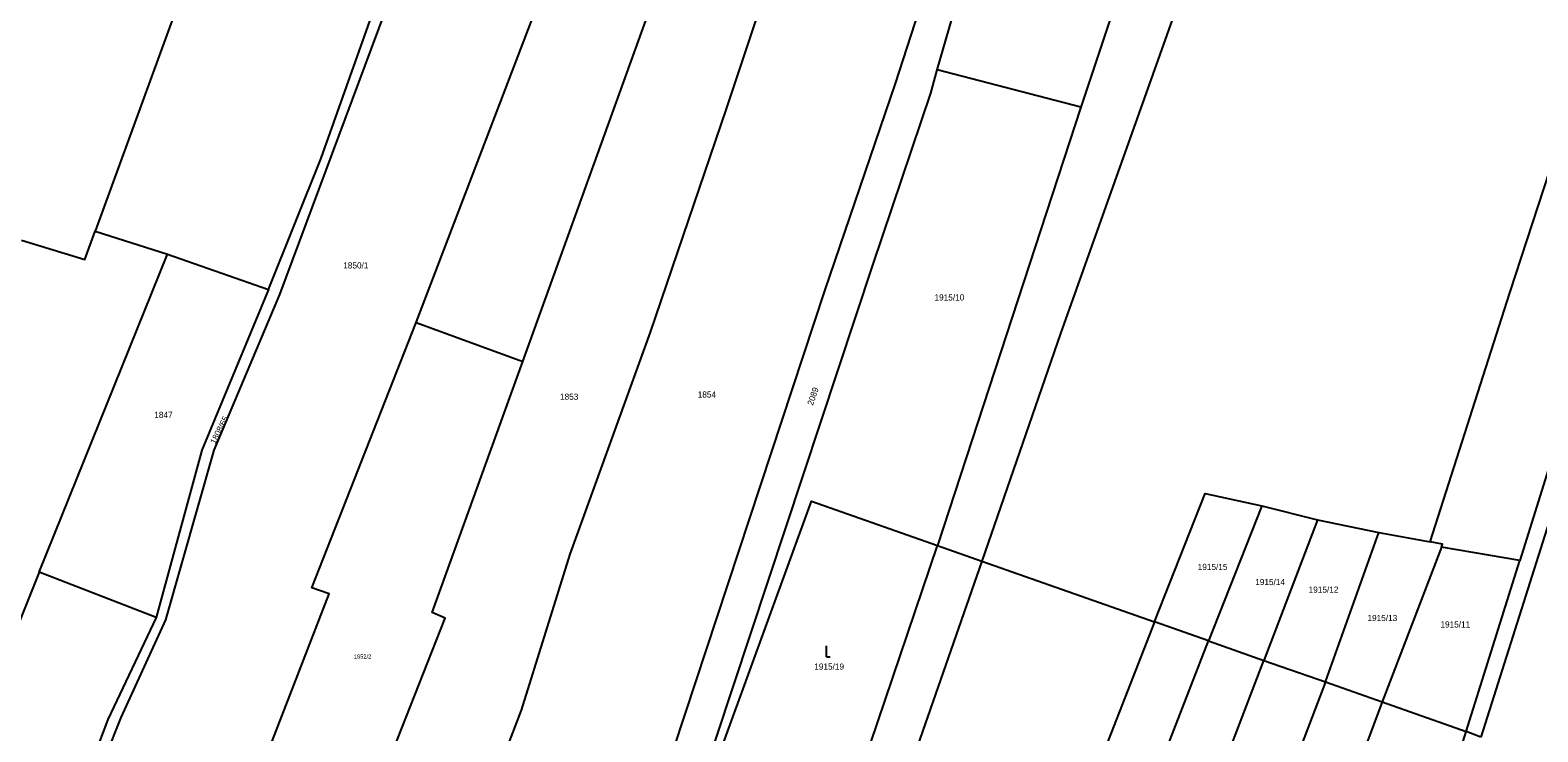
# Model space of a CAD drawing. Extents: x -679220 to -673243, y -1075091 to -1066557.
# Drawn here: x -677359.8 to -676943.8, y -1073491.5 to -1073297.9 of the extents above; entities that cross this region are included whole.
import ezdxf

# ---------------------------------------------------------------- set-up
doc = ezdxf.new("R2010")
doc.units = 0
for name, color, linetype in [('Hranice parcel', 7, 'Continuous'), ('Parcelní čísla', 7, 'Continuous'), ('Značky kultur', 7, 'Continuous')]:
    doc.layers.add(name, color=color, linetype=linetype)

msp = doc.modelspace()

# ---------------------------------------------------------------- linework, layer by layer
at = {"layer": 'Hranice parcel'}
for p, q in [((-677069.91, -1073319.09), (-677109.49, -1073308.79)), ((-677069.91, -1073319.09), (-677109.46, -1073440.06)), ((-677341.82, -1073353.29), (-677321.89, -1073359.69)), ((-677357.33, -1073447.46), (-677321.89, -1073359.69)), ((-677321.89, -1073359.69), (-677294, -1073369.43)), ((-677253.25, -1073378.52), (-677223.81, -1073389.26)), ((-677019.99, -1073429.11), (-677034.69, -1073466.38)), ((-677019.99, -1073429.11), (-677004.55, -1073432.98)), ((-677004.55, -1073432.98), (-677019.37, -1073471.77)), ((-677004.55, -1073432.98), (-676987.7, -1073436.46)), ((-677002.43, -1073477.73), (-676987.7, -1073436.46)), ((-676987.7, -1073436.46), (-676973.5, -1073439.08)), ((-677135.9, -1073518.11), (-677109.46, -1073440.06)), ((-677109.46, -1073440.06), (-677097.17, -1073444.38)), ((-676970.42, -1073440.53), (-676986.73, -1073483.26)), ((-676948.77, -1073444.19), (-676970.42, -1073440.53)), ((-677097.17, -1073444.38), (-677049.58, -1073461.14)), ((-676963.61, -1073491.41), (-676948.77, -1073444.19)), ((-677357.33, -1073447.46), (-677395.87, -1073543.8)), ((-677325.02, -1073459.98), (-677357.33, -1073447.46)), ((-677034.69, -1073466.38), (-677049.58, -1073461.14)), ((-677034.69, -1073466.38), (-677019.37, -1073471.77)), ((-677019.37, -1073471.77), (-677002.43, -1073477.73)), ((-677002.43, -1073477.73), (-676986.73, -1073483.26)), ((-676986.73, -1073483.26), (-677011.63, -1073549.35)), ((-676986.73, -1073483.26), (-676963.61, -1073491.41)), ((-676959.5, -1073492.95), (-676963.61, -1073491.41))]:
    msp.add_line(p, q, dxfattribs=at)
for points in [[(-677109.49, -1073308.79), (-677080.91, -1073210.15), (-677044.99, -1073099.31), (-677007.1, -1072994.2), (-676989.75, -1072965.34), (-676968.21, -1072939.11)], [(-676944.79, -1072950.08), (-676960.05, -1072989.81), (-677014.96, -1073154.42), (-677069.91, -1073319.09)], [(-676914.04, -1072965.12), (-676951.18, -1073046.06), (-676999.64, -1073167.96), (-677037.56, -1073274.77), (-677075.48, -1073381.61), (-677097.17, -1073444.38)], [(-677360.6, -1073577.91), (-677354.7, -1073540.24), (-677343.27, -1073509.23), (-677334.63, -1073487.55), (-677322.3, -1073460.58), (-677308.99, -1073413.79), (-677290.91, -1073370.83), (-677252.83, -1073268.54), (-677233.44, -1073217.39), (-677224.14, -1073188.44), (-677213.31, -1073160.11)], [(-677294, -1073369.43), (-677279.45, -1073333.14), (-677256.07, -1073267.05), (-677237, -1073217.18), (-677221.41, -1073172.6)], [(-677253.25, -1073378.52), (-677216.34, -1073281.75), (-677179.33, -1073184.63)], [(-677223.81, -1073389.26), (-677187.84, -1073289.61), (-677152.01, -1073189.68)], [(-677264.06, -1073589.62), (-677224.22, -1073485.56), (-677210.76, -1073442.48), (-677188.66, -1073381.24), (-677167.66, -1073319.59), (-677126.89, -1073197.06)], [(-677294.34, -1073200.19), (-677310.14, -1073246.98), (-677304.42, -1073250.66), (-677341.82, -1073353.29)], [(-677086.62, -1073206.07), (-677121.07, -1073312.55), (-677140.62, -1073369.77), (-677185.1, -1073504.75), (-677220.1, -1073606.23)], [(-676973.5, -1073439.08), (-676951.57, -1073370.32), (-676927.91, -1073298.02)], [(-676906.59, -1073301.05), (-676926.98, -1073374.45), (-676948.77, -1073444.19)], [(-677175.38, -1073507.95), (-677127.23, -1073362.44), (-677111.23, -1073315.22), (-677109.49, -1073308.79)], [(-676898.91, -1073306.59), (-676912.58, -1073344.63), (-676959.5, -1073492.95)], [(-677362.12, -1073355.77), (-677344.69, -1073361.19), (-677341.82, -1073353.29)], [(-677294, -1073369.43), (-677312.42, -1073413.79), (-677325.02, -1073459.98)], [(-677321.8, -1073568.47), (-677277.3, -1073453.37), (-677282.04, -1073451.73), (-677253.25, -1073378.52)], [(-677291.67, -1073578.1), (-677245.31, -1073460.16), (-677248.85, -1073458.52), (-677223.81, -1073389.26)], [(-677049.58, -1073461.14), (-677035.58, -1073425.72), (-677019.99, -1073429.11)], [(-677173.54, -1073508.42), (-677144.2, -1073427.83), (-677109.46, -1073440.06)], [(-676970.42, -1073440.53), (-676970.13, -1073439.72), (-676973.5, -1073439.08)], [(-677097.17, -1073444.38), (-677132.03, -1073544.52), (-677160.6, -1073621.14)], [(-677325.02, -1073459.98), (-677338.32, -1073488.07), (-677357.95, -1073539.92), (-677364.05, -1073576.72), (-677375.09, -1073604.38)], [(-677049.58, -1073461.14), (-677083.15, -1073547.2), (-677119.75, -1073635.67)], [(-677104.23, -1073641.19), (-677075.32, -1073571.14), (-677034.69, -1073466.38)], [(-677088.78, -1073646.69), (-677058.36, -1073573.83), (-677019.37, -1073471.77)], [(-677002.43, -1073477.73), (-677039.97, -1073576.48), (-677071.09, -1073652.98)], [(-676987.3, -1073560.31), (-676965.75, -1073498.5), (-676963.61, -1073491.41)]]:
    msp.add_lwpolyline(points, dxfattribs=at)
at = {"layer": 'Značky kultur'}
for q in [(-677140.07, -1073467.79), (-677139.07, -1073470.79)]:
    msp.add_line((-677140.07, -1073470.79), q, dxfattribs=at)

# ---------------------------------------------------------------- texts
at = {"layer": 'Parcelní čísla'}
for s, height, p in [('1850/1', 1.7, (-677273.39, -1073363.63)), ('1915/10', 1.7, (-677110.26, -1073372.47)), ('1853', 1.7, (-677213.58, -1073399.86)), ('1854', 1.7, (-677175.59, -1073399.25)), ('1847', 1.7, (-677325.52, -1073404.87)), ('1915/15', 1.7, (-677037.65, -1073446.84)), ('1915/14', 1.7, (-677021.78, -1073451)), ('1915/12', 1.7, (-677007.04, -1073453.11)), ('1915/13', 1.7, (-676990.81, -1073460.93)), ('1915/11', 1.7, (-676970.67, -1073462.71)), ('1852/2', 1.14, (-677270.47, -1073471.29)), ('1915/19', 1.7, (-677143.44, -1073474.34))]:
    msp.add_text(s, height=height, dxfattribs=at).set_placement(p)
for s, rotation, p in [('2089', 71, (-677143.82, -1073401.56)), ('1808/65', 63, (-677308.69, -1073412.23))]:
    msp.add_text(s, height=1.7, rotation=rotation, dxfattribs=at).set_placement(p)

doc.saveas('drawing.dxf')
